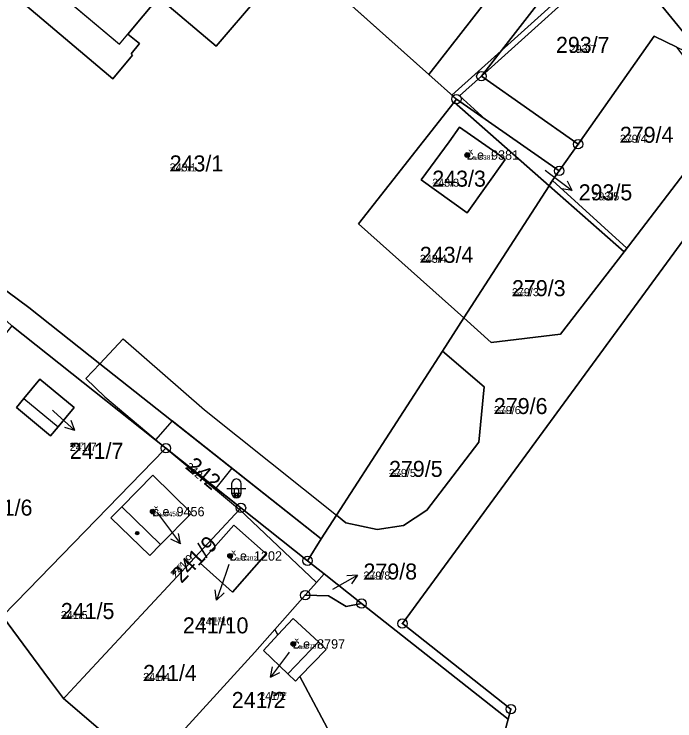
# Model space of a CAD drawing. Extents: x -759873 to -758487, y -975024 to -973516.
# Drawn here: x -759134.5 to -759064.4, y -974437.2 to -974362.2 of the extents above; entities that cross this region are included whole.
import ezdxf

# ---------------------------------------------------------------- set-up
doc = ezdxf.new("R2010")
doc.units = 0
for name, color, linetype in [('KAT_02_hranice parcel', 7, 'Continuous'), ('KAT_03_1000_st čísla parcelní', 7, 'Continuous'), ('KAT_03_1000_čísla parcelní', 7, 'Continuous'), ('KAT_03_1000_čísla popisná', 7, 'Continuous'), ('KAT_03_250_st čísla parcelní', 7, 'Continuous'), ('KAT_03_250_čísla parcelní', 7, 'Continuous'), ('KAT_03_250_čísla popisná', 7, 'Continuous'), ('KAT_03_500_st čísla parcelní', 7, 'Continuous'), ('KAT_03_500_čísla parcelní', 7, 'Continuous'), ('KAT_03_500_čísla popisná', 7, 'Continuous'), ('KAT_04_vnitřní kresba', 7, 'Continuous'), ('KAT_05_1000_značky kultur', 7, 'Continuous'), ('KAT_05_250_značky kultur', 7, 'Continuous'), ('KAT_05_500_značky kultur', 7, 'Continuous'), ('KAT_07_1000_značky budov', 7, 'Continuous'), ('KAT_07_250_značky budov', 7, 'Continuous'), ('KAT_07_500_značky budov', 7, 'Continuous'), ('KAT_10_věcná břemena', 7, 'Continuous'), ('KAT_11_značky bodu BP', 7, 'Continuous'), ('KAT_12_pomocná šipka', 7, 'Continuous'), ('KAT_14_plocha_budovy', 7, 'Continuous'), ('KAT_14_plocha_pozemek', 7, 'Continuous')]:
    doc.layers.add(name, color=color, linetype=linetype)

msp = doc.modelspace()

# ---------------------------------------------------------------- linework, layer by layer
at = {"layer": 'KAT_02_hranice parcel'}
for p, q in [((-759090.51, -974368.61), (-759115.29, -974346.47)), ((-759087.6, -974371.21), (-759090.51, -974368.61)), ((-759087.85, -974371.54), (-759087.6, -974371.21)), ((-759076.68, -974378.83), (-759087.6, -974371.21)), ((-759077.77, -974380.4), (-759087.85, -974371.54)), ((-759074.68, -974375.99), (-759076.68, -974378.83)), ((-759069.78, -974387.41), (-759061.52, -974376.58)), ((-759086.82, -974394.42), (-759077.77, -974380.4)), ((-759069.78, -974387.41), (-759077.77, -974380.4)), ((-759089.09, -974397.95), (-759086.82, -974394.42)), ((-759118.43, -974408.25), (-759134.79, -974395.25)), ((-759100.34, -974415.37), (-759089.09, -974397.95)), ((-759110.46, -974414.59), (-759118.43, -974408.25)), ((-759103.4, -974420.2), (-759110.46, -974414.59)), ((-759101.95, -974417.87), (-759100.34, -974415.37)), ((-759103.4, -974420.2), (-759101.95, -974417.87)), ((-759101.64, -974421.6), (-759103.4, -974420.2)), ((-759101.64, -974421.6), (-759097.66, -974424.74)), ((-759106.86, -974427.48), (-759103.64, -974423.85)), ((-759097.66, -974424.74), (-759082.1, -974437)), ((-759106.55, -974428.07), (-759106.86, -974427.48))]:
    msp.add_line(p, q, dxfattribs=at)
for points in [[(-759090.51, -974368.61), (-759075.8, -974349.7), (-759079.45, -974344.13)], [(-759121.24, -974365.32), (-759122.11, -974366.39), (-759121.96, -974366.53), (-759124.06, -974369.05), (-759133.19, -974361.34), (-759131.11, -974358.85), (-759122.46, -974348.54), (-759108.61, -974360.31), (-759113.09, -974365.59), (-759119.2, -974360.38), (-759122.47, -974364.3), (-759121.24, -974365.32)], [(-759074.68, -974375.99), (-759084.95, -974368.78), (-759072.61, -974352.91), (-759060.96, -974367.26)], [(-759064.2, -974365.69), (-759066.62, -974364.52), (-759074.68, -974375.99)], [(-759086.82, -974394.42), (-759097.98, -974384.46), (-759087.85, -974371.54)], [(-759082.42, -974377.6), (-759083.32, -974376.96), (-759087.26, -974374.2), (-759088.38, -974375.73), (-759091.33, -974379.79), (-759086.47, -974383.27), (-759082.42, -974377.6)], [(-759061.52, -974376.58), (-759058.24, -974378.96), (-759093.33, -974426.86), (-759081.81, -974435.94), (-759082.1, -974437)], [(-759101.95, -974417.87), (-759125.43, -974399.29), (-759132.98, -974393.31), (-759152.45, -974378.9)], [(-759076.68, -974378.83), (-759077.6, -974380.14), (-759077.77, -974380.4)], [(-759086.82, -974394.42), (-759083.9, -974397.03), (-759076.55, -974396.16), (-759069.78, -974387.41)], [(-759100.34, -974415.37), (-759099.33, -974416.17), (-759096.02, -974416.88), (-759093.21, -974416.46), (-759090.74, -974414.83), (-759085.22, -974407.61), (-759084.64, -974401.73), (-759089.09, -974397.95)], [(-759128.18, -974403.94), (-759129.87, -974405.97), (-759130.67, -974406.93), (-759134.28, -974403.93), (-759133.49, -974402.97), (-759131.79, -974400.94), (-759128.18, -974403.94)], [(-759118.43, -974408.25), (-759118.57, -974408.39), (-759133.05, -974423.28), (-759135.77, -974426.07)], [(-759123.11, -974414.46), (-759119.82, -974411.11), (-759115.7, -974415.13), (-759118.99, -974418.48), (-759120.14, -974419.63), (-759124.27, -974415.65), (-759123.11, -974414.46)], [(-759110.46, -974414.59), (-759110.61, -974414.75), (-759127.21, -974432.58), (-759129.04, -974434.55), (-759129.3, -974434.83)], [(-759111.36, -974423.52), (-759114.79, -974420.46), (-759111.21, -974416.43), (-759107.79, -974419.48), (-759111.36, -974423.52)], [(-759103.64, -974423.85), (-759102.44, -974422.49), (-759101.64, -974421.6)], [(-759097.66, -974424.74), (-759099.28, -974425.06), (-759101.18, -974423.91), (-759103.64, -974423.85)], [(-759129.3, -974434.83), (-759130.77, -974432.84), (-759135.77, -974426.07)], [(-759104.2, -974432.49), (-759101.42, -974429.6), (-759102.22, -974428.79), (-759104.91, -974426.32), (-759106.55, -974428.07)], [(-759106.86, -974427.48), (-759109, -974429.9), (-759120.38, -974442.39)], [(-759106.55, -974428.07), (-759108.08, -974429.71), (-759105.49, -974432.18), (-759104.66, -974432.96), (-759104.2, -974432.49)], [(-759091.57, -974460.59), (-759090.77, -974457.77), (-759101.31, -974437.93), (-759104.2, -974432.49)], [(-759120.38, -974442.39), (-759121.83, -974441.16), (-759125.6, -974437.96), (-759129.3, -974434.83)], [(-759082.1, -974437), (-759088.9, -974462.24), (-759091.57, -974460.59)]]:
    msp.add_lwpolyline(points, dxfattribs=at)
at = {"layer": 'KAT_03_1000_čísla popisná'}
for centre in [(-759086.45, -974377.14), (-759119.83, -974414.98), (-759111.61, -974419.69), (-759104.91, -974429.03)]:
    msp.add_circle(centre, 0.25, dxfattribs=at)
at = {"layer": 'KAT_03_250_čísla popisná'}
for centre in [(-759086.45, -974377.14), (-759119.83, -974414.98), (-759111.61, -974419.69), (-759104.91, -974429.03)]:
    msp.add_circle(centre, 0.0625, dxfattribs=at)
at = {"layer": 'KAT_03_500_čísla popisná'}
for centre in [(-759086.45, -974377.14), (-759119.83, -974414.98), (-759111.61, -974419.69), (-759104.91, -974429.03)]:
    msp.add_circle(centre, 0.125, dxfattribs=at)
at = {"layer": 'KAT_04_vnitřní kresba'}
for p, q in [((-759131.11, -974358.85), (-759123.37, -974365.38)), ((-759123.37, -974365.38), (-759122.47, -974364.3)), ((-759125.43, -974399.29), (-759122.95, -974396.64)), ((-759122.95, -974396.64), (-759114.34, -974404.18)), ((-759126.91, -974400.87), (-759125.43, -974399.29)), ((-759126.91, -974400.87), (-759124.9, -974402.79)), ((-759133.49, -974402.97), (-759129.87, -974405.97)), ((-759124.9, -974402.79), (-759118.43, -974408.25)), ((-759114.34, -974404.18), (-759100.34, -974415.37)), ((-759118.43, -974408.25), (-759110.61, -974414.75)), ((-759123.11, -974414.46), (-759118.99, -974418.48)), ((-759110.61, -974414.75), (-759102.44, -974422.49)), ((-759105.49, -974432.18), (-759102.22, -974428.79))]:
    msp.add_line(p, q, dxfattribs=at)
at = {"layer": 'KAT_05_1000_značky kultur'}
for p, q in [((-759111.451, -974412.021), (-759111.451, -974413.022)), ((-759110.449, -974413.022), (-759110.449, -974412.021)), ((-759111.951, -974412.521), (-759109.949, -974412.521))]:
    msp.add_line(p, q, dxfattribs=at)
for centre, start, end in [((-759110.95, -974412.021), 0, 180), ((-759110.95, -974413.021), 180, 359.98789)]:
    msp.add_arc(centre, 0.5, start, end, dxfattribs=at)
at = {"layer": 'KAT_05_250_značky kultur'}
for p, q in [((-759111.075, -974413.145), (-759111.075, -974413.395)), ((-759110.825, -974413.395), (-759110.825, -974413.145)), ((-759111.2, -974413.27), (-759110.7, -974413.27))]:
    msp.add_line(p, q, dxfattribs=at)
for centre, start, end in [((-759110.95, -974413.145), 0, 180), ((-759110.95, -974413.395), 180, 359.98789)]:
    msp.add_arc(centre, 0.125, start, end, dxfattribs=at)
at = {"layer": 'KAT_05_500_značky kultur'}
for p, q in [((-759111.451, -974413.02), (-759110.449, -974413.02)), ((-759111.201, -974412.77), (-759111.201, -974413.271)), ((-759110.699, -974413.271), (-759110.699, -974412.77))]:
    msp.add_line(p, q, dxfattribs=at)
for centre, start, end in [((-759110.95, -974412.77), 0, 180), ((-759110.95, -974413.27), 180, 359.98789)]:
    msp.add_arc(centre, 0.25, start, end, dxfattribs=at)
at = {"layer": 'KAT_07_1000_značky budov'}
for centre in [(-759086.457, -974377.139), (-759119.837, -974414.979), (-759121.477, -974417.259), (-759111.617, -974419.689), (-759104.917, -974429.029)]:
    msp.add_circle(centre, 0.175, dxfattribs=at)
at = {"layer": 'KAT_07_250_značky budov'}
for centre in [(-759086.452, -974377.14), (-759119.832, -974414.98), (-759121.472, -974417.26), (-759111.612, -974419.69), (-759104.912, -974429.03)]:
    msp.add_circle(centre, 0.0437, dxfattribs=at)
at = {"layer": 'KAT_07_500_značky budov'}
for centre in [(-759086.453, -974377.14), (-759119.833, -974414.98), (-759121.473, -974417.26), (-759111.613, -974419.69), (-759104.913, -974429.03)]:
    msp.add_circle(centre, 0.0875, dxfattribs=at)
at = {"layer": 'KAT_10_věcná břemena'}
for points in [[(-759088.07, -974370.79), (-759087.6, -974371.21), (-759084.55, -974373.34), (-759087.26, -974370.87), (-759084.95, -974368.78), (-759070.39, -974355.64), (-759067.65, -974353.16), (-759063.45, -974349.37), (-759063.94, -974349.01), (-759068.03, -974352.7), (-759070.77, -974355.18), (-759082.85, -974366.08)], [(-759077.77, -974380.4), (-759069.78, -974387.41), (-759069.5, -974387.04), (-759077.4, -974379.85)], [(-759103.4, -974420.2), (-759101.95, -974417.87), (-759117.76, -974405.36), (-759119.53, -974407.38), (-759118.43, -974408.25), (-759110.46, -974414.59)], [(-759111.43, -974410.37), (-759113.12, -974412.48), (-759110.46, -974414.59), (-759103.4, -974420.2), (-759101.95, -974417.87)]]:
    msp.add_lwpolyline(points, close=True, dxfattribs=at)
at = {"layer": 'KAT_11_značky bodu BP'}
for centre, radius in [((-759084.95, -974368.78), 0.5), ((-759084.95, -974368.78), 0.0303), ((-759087.6, -974371.21), 0.5), ((-759087.6, -974371.21), 0.0303), ((-759074.68, -974375.99), 0.5), ((-759074.68, -974375.99), 0.0303), ((-759076.68, -974378.83), 0.5), ((-759076.68, -974378.83), 0.0303), ((-759118.43, -974408.25), 0.5), ((-759118.43, -974408.25), 0.0303), ((-759110.46, -974414.59), 0.5), ((-759110.46, -974414.59), 0.0303), ((-759103.4, -974420.2), 0.5), ((-759103.4, -974420.2), 0.0303), ((-759103.64, -974423.85), 0.5), ((-759103.64, -974423.85), 0.0303), ((-759097.66, -974424.74), 0.5), ((-759097.66, -974424.74), 0.0303), ((-759093.33, -974426.86), 0.5), ((-759093.33, -974426.86), 0.0303), ((-759081.81, -974435.94), 0.5), ((-759081.81, -974435.94), 0.0303)]:
    msp.add_circle(centre, radius, dxfattribs=at)
at = {"layer": 'KAT_12_pomocná šipka'}
for p, q in [((-759078.18, -974378.75), (-759077.72, -974379.11)), ((-759077.72, -974379.11), (-759075.323, -974380.916)), ((-759075.323, -974380.916), (-759075.822, -974379.913)), ((-759075.323, -974380.916), (-759076.424, -974380.713)), ((-759130.48, -974404.21), (-759130.32, -974404.35)), ((-759130.32, -974404.35), (-759128.09, -974406.358)), ((-759128.09, -974406.358), (-759128.499, -974405.316)), ((-759128.09, -974406.358), (-759129.169, -974406.06)), ((-759119.43, -974415.02), (-759118.7, -974416.01)), ((-759118.7, -974416.01), (-759116.894, -974418.407)), ((-759116.894, -974418.407), (-759117.097, -974417.306)), ((-759116.894, -974418.407), (-759117.897, -974417.908)), ((-759111.75, -974420.6), (-759112.08, -974421.54)), ((-759112.08, -974421.54), (-759113.057, -974424.377)), ((-759100.71, -974423.22), (-759098.111, -974421.72)), ((-759098.111, -974421.72), (-759099.229, -974421.787)), ((-759098.111, -974421.72), (-759098.728, -974422.654)), ((-759113.057, -974424.377), (-759113.204, -974423.268)), ((-759113.057, -974424.377), (-759112.258, -974423.594)), ((-759105.53, -974430.16), (-759107.336, -974432.557)), ((-759105.33, -974429.9), (-759105.53, -974430.16)), ((-759107.336, -974432.557), (-759107.133, -974431.456)), ((-759107.336, -974432.557), (-759106.333, -974432.058))]:
    msp.add_line(p, q, dxfattribs=at)
at = {"layer": 'KAT_14_plocha_budovy'}
for points in [[(-759131.11, -974358.85), (-759123.37, -974365.38), (-759122.47, -974364.3), (-759119.2, -974360.38), (-759113.09, -974365.59), (-759108.61, -974360.31), (-759122.46, -974348.54)], [(-759088.38, -974375.73), (-759091.33, -974379.79), (-759086.47, -974383.27), (-759082.42, -974377.6), (-759083.32, -974376.96), (-759087.26, -974374.2)], [(-759119.82, -974411.11), (-759123.11, -974414.46), (-759118.99, -974418.48), (-759115.7, -974415.13)], [(-759111.21, -974416.43), (-759114.79, -974420.46), (-759111.36, -974423.52), (-759107.79, -974419.48)], [(-759104.91, -974426.32), (-759106.55, -974428.07), (-759108.08, -974429.71), (-759105.49, -974432.18), (-759102.22, -974428.79)]]:
    msp.add_lwpolyline(points, close=True, dxfattribs=at)
at = {"layer": 'KAT_14_plocha_pozemek'}
for points in [[(-759087.1, -974327.84), (-759105.25, -974307.13), (-759127.78, -974329.56), (-759113.77, -974344.59), (-759115.29, -974346.47), (-759090.51, -974368.61), (-759075.8, -974349.7), (-759079.45, -974344.13)], [(-759076.68, -974378.83), (-759074.68, -974375.99), (-759084.95, -974368.78), (-759072.61, -974352.91), (-759060.96, -974367.26), (-759057.32, -974369.03), (-759056.37, -974366.99), (-759070.29, -974349.93), (-759074.99, -974338.96), (-759079.48, -974333.82), (-759079.47, -974336.54), (-759079.45, -974344.13), (-759075.8, -974349.7), (-759090.51, -974368.61), (-759087.6, -974371.21)], [(-759090.51, -974368.61), (-759115.29, -974346.47), (-759121.28, -974341.12), (-759136.75, -974359.69), (-759152.45, -974378.9), (-759132.98, -974393.31), (-759125.43, -974399.29), (-759101.95, -974417.87), (-759100.34, -974415.37), (-759089.09, -974397.95), (-759086.82, -974394.42), (-759097.98, -974384.46), (-759087.85, -974371.54), (-759087.6, -974371.21)], [(-759121.24, -974365.32), (-759122.11, -974366.39), (-759121.96, -974366.53), (-759124.06, -974369.05), (-759133.19, -974361.34), (-759131.11, -974358.85), (-759122.46, -974348.54), (-759108.61, -974360.31), (-759113.09, -974365.59), (-759119.2, -974360.38), (-759122.47, -974364.3)], [(-759121.24, -974365.32), (-759122.47, -974364.3), (-759119.2, -974360.38), (-759113.09, -974365.59), (-759108.61, -974360.31), (-759122.46, -974348.54), (-759131.11, -974358.85), (-759133.19, -974361.34), (-759124.06, -974369.05), (-759121.96, -974366.53), (-759122.11, -974366.39)], [(-759060.96, -974367.26), (-759072.61, -974352.91), (-759084.95, -974368.78), (-759074.68, -974375.99), (-759066.62, -974364.52), (-759064.2, -974365.69)], [(-759077.6, -974380.14), (-759077.77, -974380.4), (-759069.78, -974387.41), (-759061.52, -974376.58), (-759061.03, -974373.59), (-759061.25, -974370.57), (-759062.54, -974367.9), (-759064.2, -974365.69), (-759066.62, -974364.52), (-759074.68, -974375.99), (-759076.68, -974378.83)], [(-759077.77, -974380.4), (-759077.6, -974380.14), (-759076.68, -974378.83), (-759087.6, -974371.21), (-759087.85, -974371.54)], [(-759077.77, -974380.4), (-759087.85, -974371.54), (-759097.98, -974384.46), (-759086.82, -974394.42)], [(-759082.42, -974377.6), (-759083.32, -974376.96), (-759087.26, -974374.2), (-759088.38, -974375.73), (-759091.33, -974379.79), (-759086.47, -974383.27)], [(-759082.42, -974377.6), (-759086.47, -974383.27), (-759091.33, -974379.79), (-759088.38, -974375.73), (-759087.26, -974374.2), (-759083.32, -974376.96)], [(-759089.09, -974397.95), (-759084.64, -974401.73), (-759085.22, -974407.61), (-759090.74, -974414.83), (-759093.21, -974416.46), (-759096.02, -974416.88), (-759099.33, -974416.17), (-759100.34, -974415.37), (-759101.95, -974417.87), (-759103.4, -974420.2), (-759101.64, -974421.6), (-759097.66, -974424.74), (-759082.1, -974437), (-759081.81, -974435.94), (-759093.33, -974426.86), (-759058.24, -974378.96), (-759061.52, -974376.58), (-759069.78, -974387.41), (-759076.55, -974396.16), (-759083.9, -974397.03), (-759086.82, -974394.42)], [(-759101.95, -974417.87), (-759125.43, -974399.29), (-759132.98, -974393.31), (-759152.45, -974378.9), (-759134.79, -974395.25), (-759118.43, -974408.25), (-759110.46, -974414.59), (-759103.4, -974420.2)], [(-759069.78, -974387.41), (-759077.77, -974380.4), (-759086.82, -974394.42), (-759083.9, -974397.03), (-759076.55, -974396.16)], [(-759118.43, -974408.25), (-759134.79, -974395.25), (-759143.66, -974406.38), (-759149.08, -974412.41), (-759135.77, -974426.07), (-759133.05, -974423.28), (-759118.57, -974408.39)], [(-759089.09, -974397.95), (-759100.34, -974415.37), (-759099.33, -974416.17), (-759096.02, -974416.88), (-759093.21, -974416.46), (-759090.74, -974414.83), (-759085.22, -974407.61), (-759084.64, -974401.73)], [(-759128.18, -974403.94), (-759129.87, -974405.97), (-759130.67, -974406.93), (-759134.28, -974403.93), (-759133.49, -974402.97), (-759131.79, -974400.94)], [(-759128.18, -974403.94), (-759131.79, -974400.94), (-759133.49, -974402.97), (-759134.28, -974403.93), (-759130.67, -974406.93), (-759129.87, -974405.97)], [(-759118.57, -974408.39), (-759133.05, -974423.28), (-759135.77, -974426.07), (-759130.77, -974432.84), (-759129.3, -974434.83), (-759129.04, -974434.55), (-759127.21, -974432.58), (-759110.61, -974414.75), (-759110.46, -974414.59), (-759118.43, -974408.25)], [(-759123.11, -974414.46), (-759119.82, -974411.11), (-759115.7, -974415.13), (-759118.99, -974418.48), (-759120.14, -974419.63), (-759124.27, -974415.65)], [(-759123.11, -974414.46), (-759124.27, -974415.65), (-759120.14, -974419.63), (-759118.99, -974418.48), (-759115.7, -974415.13), (-759119.82, -974411.11)], [(-759129.04, -974434.55), (-759129.3, -974434.83), (-759125.6, -974437.96), (-759121.83, -974441.16), (-759120.38, -974442.39), (-759109, -974429.9), (-759106.86, -974427.48), (-759103.64, -974423.85), (-759102.44, -974422.49), (-759101.64, -974421.6), (-759103.4, -974420.2), (-759110.46, -974414.59), (-759110.61, -974414.75), (-759127.21, -974432.58)], [(-759111.36, -974423.52), (-759114.79, -974420.46), (-759111.21, -974416.43), (-759107.79, -974419.48)], [(-759111.36, -974423.52), (-759107.79, -974419.48), (-759111.21, -974416.43), (-759114.79, -974420.46)], [(-759103.64, -974423.85), (-759101.18, -974423.91), (-759099.28, -974425.06), (-759097.66, -974424.74), (-759101.64, -974421.6), (-759102.44, -974422.49)], [(-759101.18, -974423.91), (-759103.64, -974423.85), (-759106.86, -974427.48), (-759106.55, -974428.07), (-759104.91, -974426.32), (-759102.22, -974428.79), (-759101.42, -974429.6), (-759104.2, -974432.49), (-759101.31, -974437.93), (-759090.77, -974457.77), (-759091.57, -974460.59), (-759088.9, -974462.24), (-759082.1, -974437), (-759097.66, -974424.74), (-759099.28, -974425.06)], [(-759120.38, -974442.39), (-759121.83, -974441.16), (-759125.6, -974437.96), (-759129.3, -974434.83), (-759130.77, -974432.84), (-759135.77, -974426.07), (-759136.67, -974427), (-759151.23, -974441.95), (-759139.87, -974435.29), (-759094.03, -974469.33), (-759091.57, -974460.59), (-759105.53, -974451.97)], [(-759106.55, -974428.07), (-759108.08, -974429.71), (-759105.49, -974432.18), (-759104.66, -974432.96), (-759104.2, -974432.49), (-759101.42, -974429.6), (-759102.22, -974428.79), (-759104.91, -974426.32)], [(-759090.77, -974457.77), (-759101.31, -974437.93), (-759104.2, -974432.49), (-759104.66, -974432.96), (-759105.49, -974432.18), (-759108.08, -974429.71), (-759106.55, -974428.07), (-759106.86, -974427.48), (-759109, -974429.9), (-759120.38, -974442.39), (-759105.53, -974451.97), (-759091.57, -974460.59)]]:
    msp.add_lwpolyline(points, close=True, dxfattribs=at)
msp.add_lwpolyline([(-759058.24, -974378.96), (-759093.33, -974426.86), (-759081.81, -974435.94), (-759082.1, -974437), (-759088.9, -974462.24), (-759091.57, -974460.59), (-759094.03, -974469.33), (-759139.87, -974435.29), (-759151.23, -974441.95), (-759159.88, -974450.84), (-759164.42, -974455.5), (-759159.14, -974477.67)], dxfattribs=at)

# ---------------------------------------------------------------- texts
at = {"layer": 'KAT_03_1000_st čísla parcelní'}
for s, p in [('243/3', (-759090.16, -974380.5)), ('241/10', (-759116.625, -974427.903)), ('241/2', (-759111.436, -974435.823))]:
    msp.add_text(s, height=1.7, dxfattribs=at).set_placement(p)
msp.add_text('241/9', height=1.7, rotation=46, dxfattribs=at).set_placement((-759116.771, -974422.668))
at = {"layer": 'KAT_03_1000_čísla parcelní'}
for s, p in [('293/7', (-759077.033, -974366.299)), ('279/4', (-759070.25, -974375.84)), ('243/1', (-759118.03, -974378.88)), ('293/5', (-759074.623, -974381.95)), ('243/4', (-759091.48, -974388.58)), ('279/3', (-759081.7, -974392.12)), ('279/6', (-759083.62, -974404.63)), ('241/7', (-759128.63, -974409.383)), ('279/5', (-759094.75, -974411.299)), ('241/6', (-759138.28, -974415.41)), ('279/8', (-759097.46, -974422.19)), ('241/5', (-759129.58, -974426.38)), ('241/4', (-759120.84, -974432.95))]:
    msp.add_text(s, height=1.7, dxfattribs=at).set_placement(p)
msp.add_text('242', height=1.7, rotation=320, dxfattribs=at).set_placement((-759116.436, -974410.351))
at = {"layer": 'KAT_03_1000_čísla popisná'}
for s, p in [('č.e. 9381', (-759086.45, -974377.64)), ('č.e. 9456', (-759119.83, -974415.48)), ('č.e. 1202', (-759111.61, -974420.19)), ('č.e. 8797', (-759104.91, -974429.53))]:
    msp.add_text(s, height=1, dxfattribs=at).set_placement(p)
at = {"layer": 'KAT_03_250_st čísla parcelní'}
for s, p in [('243/3', (-759090.16, -974380.5)), ('241/10', (-759113.945, -974426.628)), ('241/2', (-759107.075, -974434.548))]:
    msp.add_text(s, height=0.425, dxfattribs=at).set_placement(p)
msp.add_text('241/9', height=0.425, rotation=46, dxfattribs=at).set_placement((-759117.688, -974421.782))
at = {"layer": 'KAT_03_250_čísla parcelní'}
for s, p in [('293/7', (-759074.845, -974366.299)), ('279/4', (-759070.25, -974375.84)), ('243/1', (-759118.03, -974378.88)), ('293/5', (-759072.431, -974381.95)), ('243/4', (-759091.48, -974388.58)), ('279/3', (-759081.7, -974392.12)), ('279/6', (-759083.62, -974404.63)), ('241/7', (-759128.63, -974408.108)), ('279/5', (-759094.75, -974411.299)), ('279/8', (-759097.46, -974422.19)), ('241/5', (-759129.58, -974426.38)), ('241/4', (-759120.84, -974432.95))]:
    msp.add_text(s, height=0.425, dxfattribs=at).set_placement(p)
msp.add_text('242', height=0.425, rotation=320, dxfattribs=at).set_placement((-759116.436, -974410.351))
at = {"layer": 'KAT_03_250_čísla popisná'}
for s, p in [('č.e. 9381', (-759086.45, -974377.64)), ('č.e. 9456', (-759119.83, -974415.48)), ('č.e. 1202', (-759111.61, -974420.19)), ('č.e. 8797', (-759104.91, -974429.53))]:
    msp.add_text(s, height=0.25, dxfattribs=at).set_placement(p)
at = {"layer": 'KAT_03_500_st čísla parcelní'}
for s, p in [('243/3', (-759090.16, -974380.5)), ('241/10', (-759114.838, -974427.053)), ('241/2', (-759108.528, -974434.973))]:
    msp.add_text(s, height=0.85, dxfattribs=at).set_placement(p)
msp.add_text('241/9', height=0.85, rotation=46, dxfattribs=at).set_placement((-759117.382, -974422.078))
at = {"layer": 'KAT_03_500_čísla parcelní'}
for s, p in [('293/7', (-759075.575, -974366.299)), ('279/4', (-759070.25, -974375.84)), ('243/1', (-759118.03, -974378.88)), ('293/5', (-759073.161, -974381.95)), ('243/4', (-759091.48, -974388.58)), ('279/3', (-759081.7, -974392.12)), ('279/6', (-759083.62, -974404.63)), ('241/7', (-759128.63, -974408.533)), ('279/5', (-759094.75, -974411.299)), ('279/8', (-759097.46, -974422.19)), ('241/5', (-759129.58, -974426.38)), ('241/4', (-759120.84, -974432.95))]:
    msp.add_text(s, height=0.85, dxfattribs=at).set_placement(p)
msp.add_text('242', height=0.85, rotation=320, dxfattribs=at).set_placement((-759116.436, -974410.351))
at = {"layer": 'KAT_03_500_čísla popisná'}
for s, p in [('č.e. 9381', (-759086.45, -974377.64)), ('č.e. 9456', (-759119.83, -974415.48)), ('č.e. 1202', (-759111.61, -974420.19)), ('č.e. 8797', (-759104.91, -974429.53))]:
    msp.add_text(s, height=0.5, dxfattribs=at).set_placement(p)

doc.saveas('drawing.dxf')
